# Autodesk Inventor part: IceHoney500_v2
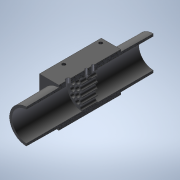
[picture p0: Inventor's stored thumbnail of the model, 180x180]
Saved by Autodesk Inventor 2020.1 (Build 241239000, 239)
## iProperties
Company: Prineton University
Created: 2020-04
Part Number: IceHoney500_v2
Material: Generic
Document SubType Name: Modeling
Designer: thiberge-admin
Density: 1 g/cm^3
Appearance: White
Author: Princeton Open Vent Monitor
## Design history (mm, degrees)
sketch "Sketch1"
  geometry: L1 (0, 25.4)-(40, 25.4); L2 (40, 25.4)-(40, 0); L3 (40, 0)-(0, 0); L4 (0, 0)-(0, 25.4); 1 further point
  constraints: 8 end point, 2 parallel, 1 coincident, 1 horizontal, 1 perpendicular
  dimensions: "d0" = 40 distance of L2.end L3.end; "d1" = 25.4 distance of L3.end L1.start
extrude "Extrusion1" new body sketch "Sketch1" distance "d2" = 25.4; taper "d3" = 0 deg
sketch "Sketch2"
  geometry: L1 (40, 0)-(0, 0) reference; L2 (40, -25.4)-(0, -25.4) reference; L3 (0, 0)-(0, -25.4) reference; L4 (40, 0)-(40, -25.4) reference; C1 r 0.889 at (17.85, -12.7); C2 r 0.889 at (22.15, -12.7); 2 further points
  constraints: 2 centre point, 2 coincident
  dimensions: "d4" = 12.7 distance from line of L1 point (17.85, -12.7) (= d5); "d5" = 12.7 distance from line of L2 point (17.85, -12.7) (derived); "d6" = 12.7 distance from line of L1 point (22.15, -12.7) (= d4); "d10" = 1.778 diameter of C1 (= d11); "d11" = 1.778 diameter of C2; "d117" = 4.3 distance of point (22.15, -12.7) point (17.85, -12.7); "d118" = 17.85 distance from line of L3 point (17.85, -12.7) (= d119); "d119" = 17.85 distance from line of L4 point (22.15, -12.7) (derived)
extrude "Extrusion2_#50 drill bit" cut sketch "Sketch2" distance "d12" = 4.572; taper "d13" = 0 deg
sketch "Sketch4"
  geometry: L1 (-25.4, 0)-(-25.4, 25.4) reference; L2 (0, 25.4)-(-25.4, 25.4) reference; L3 (0, 0)-(-25.4, 0) reference; L4 (0, 0)-(0, 25.4) reference; C1 r 1.587 at (-12.7, 12.7); 1 further point
  constraints: 1 centre point, 1 coincident
  dimensions: "d21" = 12.7 distance from line of L1 point (-12.7, 12.7) (= d24); "d22" = 12.7 distance from line of L2 point (-12.7, 12.7) (= d23); "d23" = 12.7 distance from line of L3 point (-12.7, 12.7) (derived); "d24" = 12.7 distance from line of L4 point (-12.7, 12.7) (derived); "d25" = 3.175 diameter of C1
extrude "Extrusion3" cut sketch "Sketch4" extent not by distance; stored distance "d26" = 0; taper "d27" = 0 deg
sketch "Sketch5"
  geometry: C1 r 1.587 at (-12.7, 12.7) reference; C2 r 12.7 at (-12.7, 12.7); 1 further point
  constraints: 1 centre point, 1 coincident
  dimensions: "d28" = 25.4 diameter of C2
extrude "Extrusion4" join sketch "Sketch5" distance "d29" = 21.0058; taper "d30" = 0 deg
sketch "Sketch6"
  geometry: C1 r 12.7 at (12.602, 12.602); C2 r 1.587 at (12.7, 12.7) reference; 1 further point
  constraints: 1 centre point
  dimensions: "d31" = 25.4 diameter of C1
extrude "Extrusion5" join sketch "Sketch6" distance "d32" = 21.0058; taper "d33" = 0 deg
sketch "Sketch7"
  geometry: C1 r 1.587 at (0.098, 0.098) reference; C2 r 9.525 at (0.098, 0.098); 2 further points
  constraints: 2 coincident, 1 centre point
  dimensions: "d34" = 19.05 diameter of C2
extrude "Extrusion6" cut sketch "Sketch7" distance "d35" = 21.0058; taper "d36" = 0 deg
sketch "Sketch8"
  geometry: C1 r 12.7 at (0, 0) reference; C2 r 1.587 at (0, 0) reference; C3 r 9.525 at (0, 0); 1 further point
  constraints: 1 centre point, 1 coincident
  dimensions: "d40" = 19.05 diameter of C3
extrude "Extrusion7" cut sketch "Sketch8" distance "d41" = 21.0058; taper "d42" = 0 deg
sketch "Sketch9"
  geometry: L1 (40, -25.4)-(0, -25.4) reference; L2 (40, 0)-(0, 0) reference; L3 (0, 0)-(0, -25.4) reference; L4 (40, -12.7)-(40, -25.4) reference; 4 further points
  dimensions: "d46" = 5.08 distance from line of L1 point (27.3, -20.32); "d47" = 5.08 distance from line of L1 point (12.7, -20.32) (= d46); "d48" = 5.08 distance from line of L2 point (12.7, -5.08) (= d46); "d49" = 5.08 distance from line of L2 point (27.3, -5.08) (= d46); "d50" = 12.7 distance from line of point (12.7, -5.08) L3; "d51" = 12.7 distance from line of L3 point (12.7, -20.32) (= d50); "d52" = 12.7 distance from line of L4 point (27.3, -5.08) (= d50); "d53" = 12.7 distance from line of L4 point (27.3, -20.32) (= d51)
hole "Hole2" sketch "Sketch9" at (27.3, -20.32), (12.7, -20.32), (12.7, -5.08), (27.3, -5.08) diameter "d54" = 3.302; stored, may be unused: countersink angle "d58" = 82 deg, drill point angle "d60" = 118 deg; dims "d55" = 8.3312, "d56" = 9.525, "d57" = 6.35, "d59" = 8.89
sketch "Sketch10"
  geometry: L1 (17.85, -12.7)-(17.85, -12.7); L2 (17.85, -13.7)-(17.85, -13.7); L3 (17.85, -11.7)-(17.85, -11.7); L4 (22.15, -12.7)-(22.15, -12.7); L5 (22.15, -13.7)-(22.15, -13.7); L6 (22.15, -11.7)-(22.15, -11.7); C1 r 0.889 at (17.85, -12.7) reference; C2 r 0.889 at (22.15, -12.7) reference; A1 r 1 centre (17.85, -12.7) between (17.85, -11.7) and (17.85, -13.7); A2 r 1 centre (17.85, -12.7) between (17.85, -13.7) and (17.85, -11.7); A3 r 1 centre (22.15, -12.7) between (22.15, -13.7) and (22.15, -11.7); A4 r 1 centre (22.15, -12.7) between (22.15, -11.7) and (22.15, -13.7); 3 further points
  constraints: 16 end point, 8 point on circle, 8 tangent, 4 centre point, 2 midpoint, 2 parallel, 1 horizontal, 1 point on line
  dimensions: "d61" = 0 distance of L1.start L1.end (= d63); "d62" = 4.3 distance of L4.end L1.end; "d63" = 0 distance of L4.start L4.end (derived); "d64" = 1 radius of A2; "d65" = 1 radius of A4 (= d64)
extrude "Extrusion8" cut sketch "Sketch10" distance "d66" = 2; taper "d67" = 0 deg
sketch "Sketch11"
  geometry: L1 (40, 0)-(0, 0) reference; L2 (0, 0)-(0, -25.4) reference; C1 r 0.794 at (41.275, -12.7) reference; C2 r 0.794 at (85.725, -12.7) reference; 6 further points
  constraints: 1 horizontal, 1 vertical, 5 other
  dimensions: "d70" = 25 distance of point (38.5, -6.7) point (63.5, -6.7); "d73" = 12 distance of point (38.5, -6.7) point (38.5, -18.7); "d76" = 6 vertical distance of C1.centre point (38.5, -6.7) (= d77); "d77" = 6 vertical distance of C1.centre point (38.5, -18.7) (derived); "d78" = 2.775 horizontal distance of point (38.5, -6.7) C1.centre (= d79); "d79" = 2.775 horizontal distance of point (88.5, -6.7) C2.centre (derived)
hole "Hole3" sketch "Sketch11" at (38.5, -6.7), (38.5, -18.7), (63.5, -6.7), (63.5, -18.7), (88.5, -6.7), (88.5, -18.7) diameter "d80" = 2.15646; stored, may be unused: countersink angle "d84" = 82 deg, drill point angle "d86" = 118 deg; dims "d81" = 5.6896, "d82" = 9.525, "d83" = 6.35, "d85" = 7.62
sketch "Sketch19"
  geometry: C1 r 3 at (0, 0) reference; C2 r 11.265 at (0, 0); C3 r 12.7 at (0, 0) reference; 1 further point
  constraints: 1 centre point, 1 coincident
  dimensions: "d137" = 22.5298 diameter of C2
extrude "Extrusion16" cut sketch "Sketch19" distance "d138" = 21.0058; taper "d139" = 0 deg
chamfer "Chamfer7" distance "d140" = 0.2667; stored, may be unused: second distance "d141" = 21.0058, angle "d142" = 45 deg
sketch "Sketch20"
  geometry: C1 r 9.524 at (0.098, 0.098) reference; C2 r 11.265 at (0.098, 0.098); C3 r 12.7 at (0, 0) reference; 2 further points
  constraints: 2 coincident, 1 centre point
  dimensions: "d143" = 22.5298 diameter of C2
extrude "Extrusion17" cut sketch "Sketch20" distance "d144" = 21.0058; taper "d145" = 0 deg
chamfer "Chamfer8" distance "d146" = 0.2667; stored, may be unused: second distance "d147" = 21.0058, angle "d148" = 45 deg
sketch "Sketch21" dims "d163" = 25.4, "d170" = 25.4, "d179" = 25.4, "d186" = 25.4, "d196" = 25.4, "d205" = 25.4, "d214" = 25.4
  geometry: L1 (-12.7, -12.7)-(-12.7, 12.7) reference; L2 (12.7, 12.7)-(-12.7, 12.7) reference; C1 r 1.587 at (0, 0); C2 r 1.587 at (0, 0) reference; C3 r 1.587 at (0, 3.725); C4 r 1.587 at (0, -3.725); C5 r 1.587 at (0, -7.45); C6 r 1.587 at (3.226, 1.863); C7 r 1.587 at (3.226, 5.588); C8 r 1.587 at (3.226, -1.862); C9 r 1.587 at (3.226, -5.587); C10 r 1.587 at (-3.185, 5.657); C11 r 1.587 at (-3.185, 1.932); C12 r 1.587 at (-3.185, -1.793); C13 r 1.587 at (-3.185, -5.518); C14 r 1.587 at (-6.411, 3.795); C15 r 1.587 at (-6.411, 0.07); C16 r 1.587 at (-6.411, -3.655); C17 r 1.587 at (6.452, 3.725); C18 r 1.587 at (6.452, 0); C19 r 1.587 at (6.452, -3.725); 2 further points
  constraints: 18 centre point, 7 vertical, 1 coincident, 1 concentric, 26 other
  dimensions: "d160" = 3.725 distance of C1.centre C3.centre; "d167" = 3.725 distance of C1.centre C4.centre (= d160); "d172" = 3.725 distance of C6.centre C1.centre (= d160); "d173" = 3.725 distance of C3.centre C6.centre (= d172); "d176" = 3.725 distance of C6.centre C7.centre (= d160); "d183" = 3.725 distance of C6.centre C8.centre (= d176); "d189" = 3.725 distance of C3.centre C10.centre (= d188); "d193" = 3.725 distance of C10.centre C11.centre (= d176); "d198" = 3.725 distance of C14.centre C11.centre (= d160); "d199" = 3.725 distance of C10.centre C14.centre (= d160); "d202" = 3.725 distance of C14.centre C15.centre (= d160); "d207" = 3.725 distance of C17.centre C6.centre (= d160); "d208" = 3.725 distance of C7.centre C17.centre (= d160); "d211" = 3.725 distance of C17.centre C18.centre (= d160); "d235" = 3.175 diameter of C5; "d236" = 3.175 diameter of C10 (= d235); "d237" = 3.175 diameter of C7 (= d235); "d238" = 3.175 diameter of C16 (= d235); "d239" = 3.175 diameter of C17 (= d237)
extrude "Extrusion18" cut sketch "Sketch21" distance "d216" = 76.2; taper "d217" = 0 deg
sketch "Sketch24"
  geometry: C1 r 1.587 at (0, 0) reference; C2 r 9.525 at (0, 0); 1 further point
  constraints: 1 centre point, 1 coincident
extrude "Extrusion21" cut sketch "Sketch24" distance "d226" = 15; taper "d227" = 0 deg
sketch "Sketch25"
  geometry: C1 r 1.587 at (0, 0) reference; C2 r 9.525 at (0, 0); 1 further point
  constraints: 1 centre point, 1 coincident
extrude "Extrusion22" cut sketch "Sketch25" distance "d228" = 15; taper "d229" = 0 deg
sketch "Sketch22"
  geometry: C1 r 1.587 at (0, 3.725) reference; C2 r 1.587 at (-3.226, 5.588) reference; C3 r 1.587 at (0, 7.45); 1 further point
  constraints: 1 centre point
  dimensions: "d218" = 3.175 diameter of C1 (derived); "d219" = 3.175 diameter of C3 (= d218); "d220" = 3.725 distance of C1.centre C2.centre (derived); "d221" = 3.725 distance of C3.centre C1.centre (= d220)
extrude "Extrusion19" cut sketch "Sketch22" distance "d222" = 18.9; taper "d223" = 0 deg
sketch "Sketch23"
  geometry: C1 r 1.587 at (0, 7.9) reference; 1 further point
extrude "Extrusion20" cut sketch "Sketch23" distance "d224" = 18.9; taper "d225" = 0 deg
sketch "Sketch29"
  geometry: C1 r 1.587 at (0, 7.408); C2 r 1.587 at (0, 3.725) reference; 2 further points
  constraints: 1 centre point, 1 coincident
  dimensions: "d289" = 3.683 distance of C1.centre C2.centre
hole "Hole6" sketch "Sketch29" diameter "d271" = 3.175; stored, may be unused: countersink angle "d275" = 82 deg, drill point angle "d277" = 118 deg; dims "d272" = 2.54, "d273" = 9.525, "d274" = 6.35, "d276" = 3.8
sketch "Sketch30"
  geometry: C1 r 1.587 at (0, 3.725) reference; A1 r 1.338 centre (0, 8.671) between (0, 7.333) and (0, 7.333); 2 further points
  constraints: 2 point on circle, 1 centre point
  dimensions: "d290" = 3.683 distance of C1.centre point (0, 7.408)
hole "Hole7" sketch "Sketch30" diameter "d278" = 3.175; stored, may be unused: countersink angle "d282" = 82 deg, drill point angle "d284" = 118 deg; dims "d279" = 2.54, "d280" = 9.525, "d281" = 6.35, "d283" = 3.8
sketch "Sketch27"
  geometry: L1 (40, 1.27)-(0, 1.27); L2 (0, 1.27)-(0, -25.4); L3 (40, 1.27)-(40, -25.4); L4 (40, -25.4)-(0, -25.4) reference; L5 (40, 0)-(0, 0) reference; L6 (0, 0)-(0, -25.4) reference; L7 (40, -25.4)-(0, -25.4) reference; L8 (40, 0)-(40, -25.4) reference; C1 r 1 at (17.85, -12.7); C2 r 0.889 at (17.85, -12.7) reference; C3 r 0.889 at (22.15, -12.7) reference; C4 r 0.889 at (17.85, -12.7) reference; 5 further points
  constraints: 6 end point, 1 centre point, 1 coincident, 1 horizontal, 1 vertical, 3 other
  dimensions: "d244" = 23.876 distance of point (2.921, -2.54) point (26.797, -2.54); "d245" = 20.32 distance of point (2.921, -2.54) point (2.921, -22.86); "d248" = 2.921 distance from line of L2 point (2.921, -22.86) (derived); "d249" = 13.203 distance from line of L3 point (26.797, -22.86) (derived); "d303" = 2.54 distance from line of L4 point (2.921, -22.86); "d306" = 20.32 distance of point (26.797, -22.86) point (26.797, -2.54) (derived); "d309" = 2.54 distance from line of L4 point (26.797, -22.86) (derived); "d311" = 2.921 distance from line of L6 point (2.921, -2.54); "d312" = 14.929 horizontal distance of point (2.921, -2.54) C1.centre (derived); "d314" = 2.54 distance from line of point (2.921, -2.54) L5
hole "Hole4" sketch "Sketch27" diameter "d251" = 2.15646; stored, may be unused: countersink angle "d255" = 82 deg, drill point angle "d257" = 118 deg; dims "d252" = 2.54, "d253" = 9.525, "d254" = 6.35, "d256" = 5.08
sketch "Sketch28"
  geometry: L1 (40, -25.4)-(0, -25.4) reference; L2 (40, 0)-(0, 0) reference; L3 (40, 0)-(40, -25.4) reference; C1 r 1 at (22.15, -12.7); 2 further points
  constraints: 1 centre point
  dimensions: "d269" = 11.7438 distance of C1.centre point (33.894, -12.7); "d270" = 12.7 distance from line of L1 point (33.894, -12.7); "d336" = 12.7 distance from line of L2 point (33.894, -12.7) (derived); "d337" = 6.1062 distance from line of L3 point (33.894, -12.7)
hole "Hole5_#30 drillbit" sketch "Sketch28" at (33.894, -12.7) diameter "d262" = 3.2639; stored, may be unused: countersink angle "d266" = 82 deg, drill point angle "d268" = 118 deg; dims "d263" = 2.54, "d264" = 9.525, "d265" = 6.35, "d267" = 5.08
sketch "Sketch32"
  geometry: C1 r 1.632 at (33.894, -12.7) reference; C2 r 0.794 at (33.894, -12.7); 1 further point
  constraints: 1 centre point, 1 coincident
  dimensions: "d291" = 1.5875 diameter of C2
extrude "Extrusion25" cut sketch "Sketch32" distance "d292" = 6.35; taper "d293" = 0 deg
sketch "Sketch31"
  geometry: C1 r 0.794 at (0, 7.408); C2 r 1.587 at (0, 7.408); 2 further points
  constraints: 2 centre point, 1 coincident
  dimensions: "d285" = 1.5875 diameter of C1; "d343" = 3.175 diameter of C2
extrude "Extrusion24" cut sketch "Sketch31" stored distance "d287" = 25.4; taper "d288" = 0 deg
sketch "Sketch33"
  geometry: C1 r 0.889 at (22.15, -12.7) reference; C2 r 0.889 at (17.85, -12.7) reference; 3 further points
  constraints: 2 coincident
hole "Hole8_#47 drillbit" sketch "Sketch33" at (22.15, -12.7), (17.85, -12.7) diameter "d294" = 1.9939; stored, may be unused: countersink angle "d298" = 82 deg, drill point angle "d300" = 118 deg; dims "d295" = 19.05, "d296" = 9.525, "d297" = 6.35, "d299" = 5
sketch "Sketch35"
  geometry: L1 (0, 0)-(40, 0) reference; L2 (40, 0)-(40, 25.4) reference; 2 further points
  dimensions: "d318" = 19.05 distance of point (14.465, 5.08) point (33.515, 5.08); "d319" = 5.08 distance from line of L1 point (33.515, 5.08); "d320" = 5.08 distance from line of L1 point (14.465, 5.08) (derived); "d321" = 6.485 distance from line of L2 point (33.515, 5.08)
hole "Hole9" sketch "Sketch35" at (14.465, 5.08), (33.515, 5.08) diameter "d322" = 2.15646; stored, may be unused: countersink angle "d326" = 82 deg, drill point angle "d328" = 118 deg; dims "d323" = 5.6896, "d324" = 3.7084, "d325" = 6.35, "d327" = 3.81
sketch "Sketch36"
  geometry: C1 r 1.078 at (-14.465, 5.08) reference; C2 r 1.078 at (-33.515, 5.08) reference; 3 further points
  constraints: 2 coincident
hole "Hole10" sketch "Sketch36" at (-14.465, 5.08), (-33.515, 5.08) diameter "d329" = 2.15646; stored, may be unused: countersink angle "d333" = 82 deg, drill point angle "d335" = 118 deg; dims "d330" = 5.6896, "d331" = 3.7084, "d332" = 6.35, "d334" = 3.81
sketch "Sketch37"
  geometry: C1 r 0.997 at (17.85, -12.7) reference; C2 r 0.997 at (22.15, -12.7) reference; C3 r 1.632 at (33.894, -12.7) reference; C4 r 1.7 at (17.85, -12.7); C5 r 1.7 at (22.15, -12.7); C6 r 2.2 at (33.894, -12.7); 1 further point
  constraints: 3 centre point, 3 coincident
  dimensions: "d338" = 3.4 diameter of C4; "d339" = 3.4 diameter of C5 (derived); "d340" = 4.4 diameter of C6
extrude "Extrusion27" cut sketch "Sketch37" distance "d341" = 1; taper "d342" = 0 deg
sketch "Sketch34"
  geometry: C1 r 2.2 at (33.894, -12.7); C2 r 1.632 at (33.894, -12.7) reference; 1 further point
  constraints: 1 centre point, 1 coincident
  dimensions: "d315" = 4.4 diameter of C1
extrude "Extrusion26" cut sketch "Sketch34" distance "d316" = 1.25; taper "d317" = 0 deg
body "Solid1"
node "Projected Loop1"
node "Projected Loop4"
other parameters: "d188" = 3.725 (= d160)
